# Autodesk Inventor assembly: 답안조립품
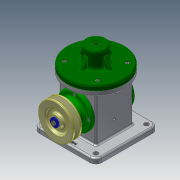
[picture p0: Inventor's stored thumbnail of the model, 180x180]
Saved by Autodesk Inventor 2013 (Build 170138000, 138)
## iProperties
Created: 2021-05
Part Number: 답안조립품
Document SubType Name: Assembly
Designer: a
Author: a
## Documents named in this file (19)
- C:\Users\a\Desktop\710506V1017\답안조립품.iam
- C:\Users\a\Desktop\710506V1017\본체.ipt
- C:\Users\a\Desktop\710506V1017\편심축.ipt
- C:\Users\a\Desktop\710506V1017\키 4 x 4 x 12.ipt
- C:\Users\a\Desktop\710506V1017\V-벨트풀리.ipt
- C:\Users\a\Desktop\710506V1017\와셔 4x16.ipt
- C:\Users\a\Desktop\710506V1017\앞커버.ipt
- C:\Users\a\Desktop\710506V1017\베어링 17 x 40 x 12.ipt
- C:\Users\a\Desktop\710506V1017\오일 실 17 30 8.ipt
- C:\Users\a\Desktop\710506V1017\뒤커버.ipt
- C:\Users\a\Desktop\710506V1017\덮개.ipt
- C:\Users\a\Desktop\710506V1017\링크.ipt
- C:\Users\a\Desktop\710506V1017\슬라이더.ipt
- C:\Users\a\Desktop\710506V1017\클레비스 핀 6 x 22.ipt
- 클레비스 핀 6 x 22.ipt
- C:\Users\a\Desktop\710506V1017\E-링.ipt
- C:\Users\a\Desktop\710506V1017\볼트 M4 x 10.ipt
- C:\Users\a\Desktop\710506V1017\볼트 M4 x 12.ipt
- 볼트 M4 x 12.ipt
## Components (2 placed, 2 different names)
1. V-벨트풀리:1
2. E-링:1 — 각도:3
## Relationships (1: Angle 1)
- 각도:3 [Angle]: E-링:1
